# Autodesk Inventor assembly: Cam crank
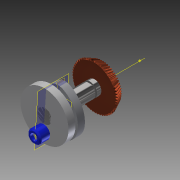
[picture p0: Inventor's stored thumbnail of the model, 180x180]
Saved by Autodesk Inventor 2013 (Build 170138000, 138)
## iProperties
Created: 2008-07
Part Number: Cam crank
Document SubType Name: Assembly
Designer: tangg
Mass: 210.119 g
Surface Area: 145.448 cm^2
Volume: 32.7179 cm^3
Density: 6.42214 g/cm^3
Author: tangg
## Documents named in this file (6)
- C:\Users\boganb\Documents\B2 Design\Goodyear\2013 Tutorial Files\Dynamic Simulation 1 and 2\Cam crank.iam
- C:\Users\boganb\Documents\B2 Design\Goodyear\2013 Tutorial Files\Dynamic Simulation 1 and 2\Crank shaft.ipt
- C:\Users\boganb\Documents\B2 Design\Goodyear\2013 Tutorial Files\Dynamic Simulation 1 and 2\Roller.ipt
- C:\Users\boganb\Documents\B2 Design\Goodyear\2013 Tutorial Files\Dynamic Simulation 1 and 2\Eccentric.ipt
- C:\Users\boganb\Documents\B2 Design\Goodyear\2013 Tutorial Files\Dynamic Simulation 1 and 2\Bevel Gear21.ipt
- C:\Users\boganb\Documents\B2 Design\Goodyear\2013 Tutorial Files\Dynamic Simulation 1 and 2\Cam  lobe.ipt
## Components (5 placed, 5 different names)
1. Crank shaft:1 — Flush:1, Mate:4, Mate:7, Mate:8, Flush:3, Mate:9
2. Roller:1 — Mate:2, Mate:3
3. Eccentric:1 — Mate:2, Mate:3, Flush:1, Mate:4, Mate:10
4. Bevel Gear2:1 — Mate:8, Flush:3
5. Cam  lobe:1 — Mate:9, Mate:10
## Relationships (9: Mate 7, Flush 2)
- Mate:2: Roller:1 ↔ Eccentric:1
- Mate:3: Roller:1 ↔ Eccentric:1
- Flush:1: Crank shaft:1 ↔ Eccentric:1
- Mate:4: Crank shaft:1 ↔ Eccentric:1
- Mate:7: Crank shaft:1
- Mate:8: Crank shaft:1 ↔ Bevel Gear2:1
- Flush:3: Crank shaft:1 ↔ Bevel Gear2:1
- Mate:9: Crank shaft:1 ↔ Cam  lobe:1
- Mate:10: Eccentric:1 ↔ Cam  lobe:1
